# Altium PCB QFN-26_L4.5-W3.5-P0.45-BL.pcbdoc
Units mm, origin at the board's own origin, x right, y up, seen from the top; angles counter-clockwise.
Board outline 17.8 x 17.2 mm, 2 copper layers (Top Layer, Bottom Layer), stack 0 mm thick; 1 components, 0 nets, 26 pads, 0 vias.
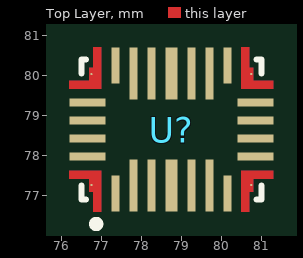
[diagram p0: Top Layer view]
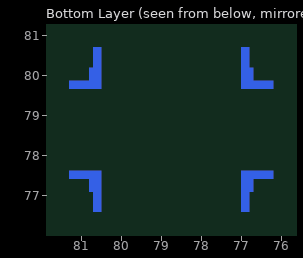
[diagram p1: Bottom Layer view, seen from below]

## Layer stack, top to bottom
Top Layer: signal copper (thickness not stored)
Bottom Layer: signal copper (thickness not stored)

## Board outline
87.65,69.85 69.85,69.85 69.85,87.055 87.65,87.055

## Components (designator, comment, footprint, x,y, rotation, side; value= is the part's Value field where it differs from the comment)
U? "" QFN-26_L4.5-W3.5-P0.45-BL 78.75,78.65 r0 top

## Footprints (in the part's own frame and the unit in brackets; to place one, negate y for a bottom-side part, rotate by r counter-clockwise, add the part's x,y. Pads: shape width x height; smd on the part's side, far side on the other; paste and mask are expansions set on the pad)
QFN-26_L4.5-W3.5-P0.45-BL [mm]
  round 0.053 smd: 1(-1.998,-1.387) 9(1.997,-1.387) 14(1.997,1.387) 22(-1.997,1.387)
  rect 0.2x0.9 smd paste+0 mask+0.05: 2(-1.4,-1.6) 8(1.4,-1.6) 15(1.4,1.6) 21(-1.4,1.6)
  rect 0.2x1.3 smd paste+0 mask+0.05: 3(-0.95,-1.4) 4(-0.5,-1.4) 6(0.5,-1.4) 7(0.95,-1.4) 16(0.95,1.4) 17(0.5,1.4) 19(-0.5,1.4) 20(-0.95,1.4)
  rect 0.3x1.3 smd paste+0 mask+0.05: 5(0,-1.4) 18(0,1.4)
  rect 0.9x0.2 smd paste+0 mask+0.05: 10(2.1,-0.675) 11(2.1,-0.225) 12(2.1,0.225) 13(2.1,0.675) 23(-2.1,0.675) 24(-2.1,0.225) 25(-2.1,-0.225) 26(-2.1,-0.675)
  Top Layer region: 1.75,2.055 1.75,1.025 2.55,1.025 2.55,1.225 2.05,1.225 2.05,1.55 1.95,1.55 1.95,2.055
  Top Layer region: 1.75,-2.055 1.75,-1.025 2.55,-1.025 2.55,-1.225 2.05,-1.225 2.05,-1.55 1.95,-1.55 1.95,-2.055
  Top Layer region: -1.75,-2.055 -1.75,-1.025 -2.55,-1.025 -2.55,-1.225 -2.05,-1.225 -2.05,-1.55 -1.95,-1.55 -1.95,-2.055
  Top Layer region: -1.75,2.055 -1.75,1.025 -2.55,1.025 -2.55,1.225 -2.05,1.225 -2.05,1.55 -1.95,1.55 -1.95,2.055
  Bottom Layer region: 1.75,2.055 1.75,1.025 2.55,1.025 2.55,1.225 2.05,1.225 2.05,1.55 1.95,1.55 1.95,2.055
  Bottom Layer region: 1.75,-2.055 1.75,-1.025 2.55,-1.025 2.55,-1.225 2.05,-1.225 2.05,-1.55 1.95,-1.55 1.95,-2.055
  Bottom Layer region: -1.75,-2.055 -1.75,-1.025 -2.55,-1.025 -2.55,-1.225 -2.05,-1.225 -2.05,-1.55 -1.95,-1.55 -1.95,-2.055
  Bottom Layer region: -1.75,2.055 -1.75,1.025 -2.55,1.025 -2.55,1.225 -2.05,1.225 -2.05,1.55 -1.95,1.55 -1.95,2.055
  Multi-Layer region: 1.75,2.055 1.75,1.025 2.55,1.025 2.55,1.225 2.05,1.225 2.05,1.55 1.95,1.55 1.95,2.055
  Multi-Layer region: 1.75,-2.055 1.75,-1.025 2.55,-1.025 2.55,-1.225 2.05,-1.225 2.05,-1.55 1.95,-1.55 1.95,-2.055
  Multi-Layer region: -1.75,-2.055 -1.75,-1.025 -2.55,-1.025 -2.55,-1.225 -2.05,-1.225 -2.05,-1.55 -1.95,-1.55 -1.95,-2.055
  Multi-Layer region: -1.75,2.055 -1.75,1.025 -2.55,1.025 -2.55,1.225 -2.05,1.225 -2.05,1.55 -1.95,1.55 -1.95,2.055
  silkscreen extent -2.25,-2.45 2.25,1.75

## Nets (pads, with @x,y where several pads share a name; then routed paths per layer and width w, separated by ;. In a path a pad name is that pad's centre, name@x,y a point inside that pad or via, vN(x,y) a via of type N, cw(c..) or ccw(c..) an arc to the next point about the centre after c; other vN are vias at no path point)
pads on no net: U?.1 U?.2 U?.3 U?.4 U?.5 U?.6 U?.7 U?.8 U?.9 U?.10 U?.11 U?.12 U?.13 U?.14 U?.15 U?.16 U?.17 U?.18 U?.19 U?.20 U?.21 U?.22 U?.23 U?.24 U?.25 U?.26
